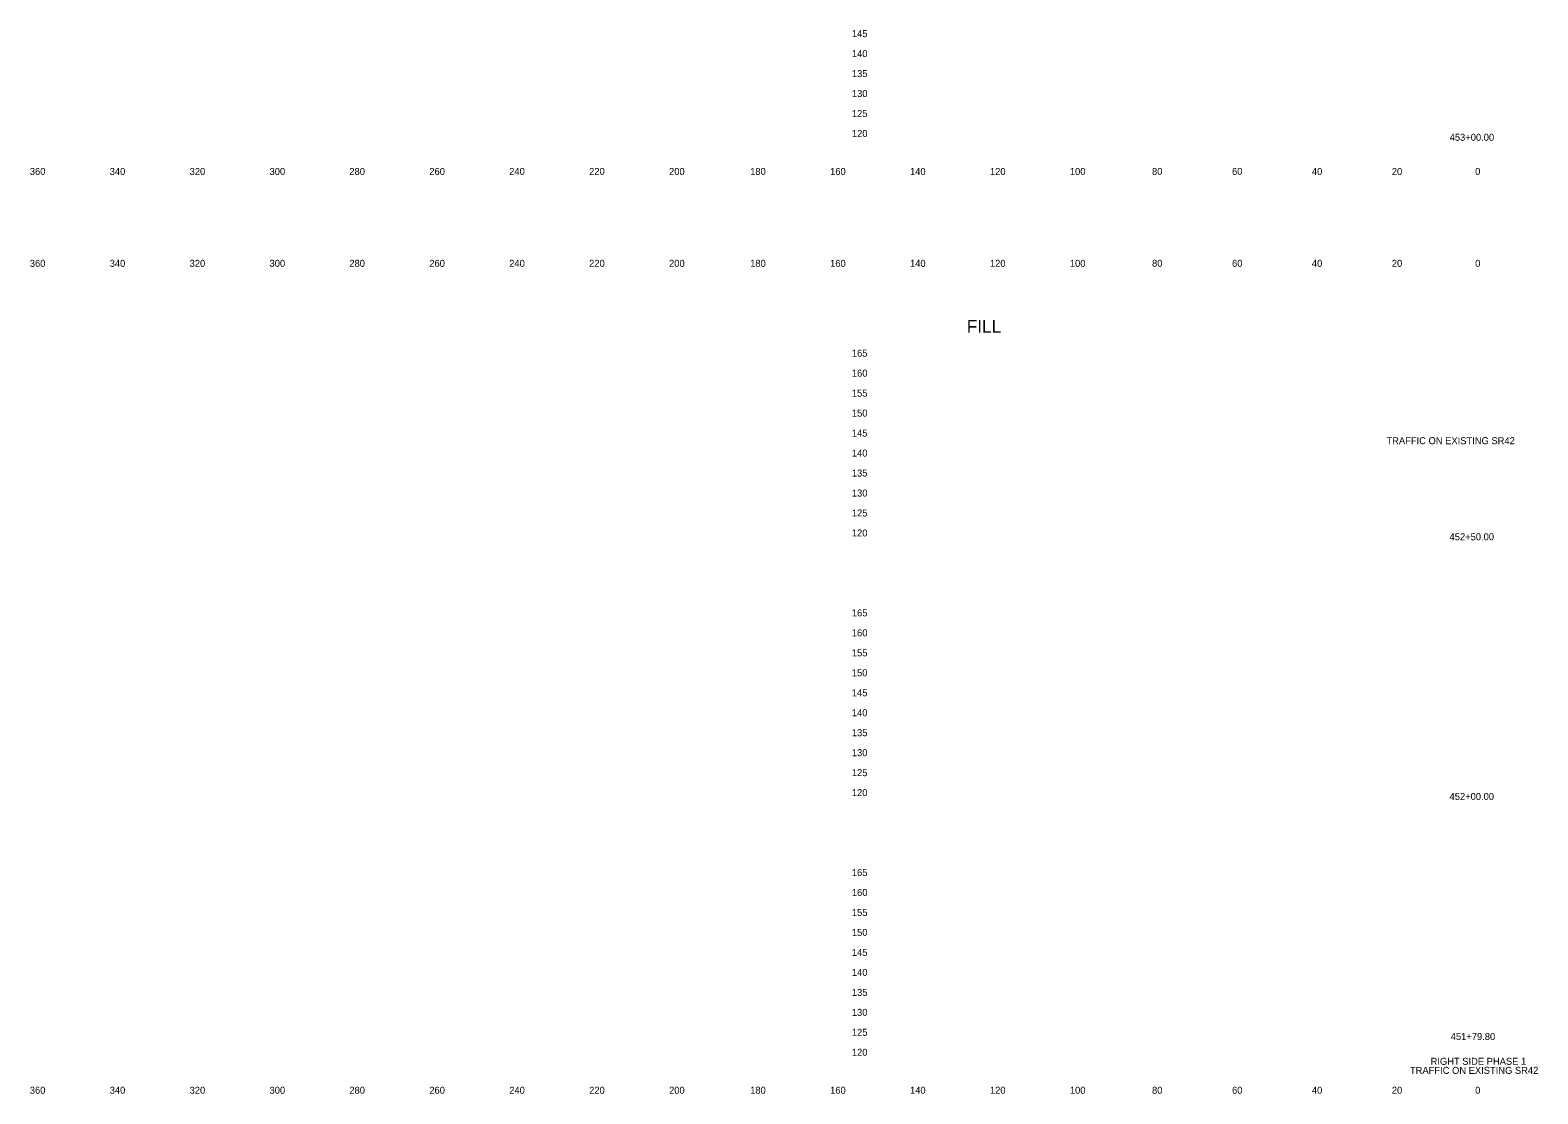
# Model space of a CAD drawing. Extents: x 21281 to 22024, y 6472 to 15198.
# Drawn here: x 21280.5 to 21657.8, y 6475.3 to 6741.6 of the extents above; entities that cross this region are included whole.
import ezdxf

# ---------------------------------------------------------------- set-up
doc = ezdxf.new("R2010")
doc.units = 0
for name, color, linetype in [('XS_SHEET_LABELS_ELEVATION', 7, 'Continuous'), ('XS_SHEET_LABELS_OFFSET', 7, 'Continuous'), ('XS_SHEET_LABELS_STATION', 7, 'Continuous')]:
    doc.layers.add(name, color=color, linetype=linetype)

msp = doc.modelspace()

# ---------------------------------------------------------------- texts
at = {"layer": 'XS_SHEET_LABELS_ELEVATION'}
for s, p in [('  145  ', (21484.84, 6739.84)), ('  140  ', (21484.84, 6734.84)), ('  135  ', (21484.84, 6729.84)), ('  130  ', (21484.84, 6724.84)), ('  125  ', (21484.84, 6719.84)), ('  120  ', (21484.84, 6714.84)), ('  165  ', (21484.84, 6659.84)), ('  160  ', (21484.84, 6654.84)), ('  155  ', (21484.84, 6649.84)), ('  150  ', (21484.84, 6644.84)), ('  145  ', (21484.84, 6639.84)), ('  140  ', (21484.84, 6634.84)), ('  135  ', (21484.84, 6629.84)), ('  130  ', (21484.84, 6624.84)), ('  125  ', (21484.84, 6619.84)), ('  120  ', (21484.84, 6614.84)), ('  165  ', (21484.84, 6594.84)), ('  160  ', (21484.84, 6589.84)), ('  155  ', (21484.84, 6584.84)), ('  150  ', (21484.84, 6579.84)), ('  145  ', (21484.84, 6574.84)), ('  140  ', (21484.84, 6569.84)), ('  135  ', (21484.84, 6564.84)), ('  130  ', (21484.84, 6559.84)), ('  125  ', (21484.84, 6554.84)), ('  120  ', (21484.84, 6549.84)), ('  165  ', (21484.84, 6529.84)), ('  160  ', (21484.84, 6524.84)), ('  155  ', (21484.84, 6519.84)), ('  150  ', (21484.84, 6514.84)), ('  145  ', (21484.84, 6509.84)), ('  140  ', (21484.84, 6504.84)), ('  135  ', (21484.84, 6499.84)), ('  130  ', (21484.84, 6494.84)), ('  125  ', (21484.84, 6489.84)), ('  120  ', (21484.84, 6484.84))]:
    msp.add_text(s, height=1.75, dxfattribs=at).set_placement(p)
at = {"layer": 'XS_SHEET_LABELS_OFFSET'}
for s, height, p in [('  360  ', 1.75, (21279.14, 6705.34)), ('  340  ', 1.75, (21299.13, 6705.34)), ('  320  ', 1.75, (21319.13, 6705.34)), ('  300  ', 1.75, (21339.13, 6705.34)), ('  280  ', 1.75, (21359.1, 6705.34)), ('  260  ', 1.75, (21379.11, 6705.34)), ('  240  ', 1.75, (21399.1, 6705.34)), ('  220  ', 1.75, (21419.1, 6705.34)), ('  200  ', 1.75, (21439.1, 6705.34)), ('  180  ', 1.75, (21459.39, 6705.34)), ('  160  ', 1.75, (21479.4, 6705.34)), ('  140  ', 1.75, (21499.39, 6705.34)), ('  120  ', 1.75, (21519.39, 6705.34)), ('  100  ', 1.75, (21539.39, 6705.34)), ('  80  ', 1.75, (21559.95, 6705.34)), ('  60  ', 1.75, (21579.97, 6705.34)), ('  40  ', 1.75, (21599.95, 6705.34)), ('  20  ', 1.75, (21619.95, 6705.34)), ('  0  ', 1.75, (21640.81, 6705.34)), ('  0  ', 1.75, (21640.81, 6705.34)), ('  360  ', 1.75, (21279.14, 6682.34)), ('  340  ', 1.75, (21299.13, 6682.34)), ('  320  ', 1.75, (21319.13, 6682.34)), ('  300  ', 1.75, (21339.13, 6682.34)), ('  280  ', 1.75, (21359.1, 6682.34)), ('  260  ', 1.75, (21379.11, 6682.34)), ('  240  ', 1.75, (21399.1, 6682.34)), ('  220  ', 1.75, (21419.1, 6682.34)), ('  200  ', 1.75, (21439.1, 6682.34)), ('  180  ', 1.75, (21459.39, 6682.34)), ('  160  ', 1.75, (21479.4, 6682.34)), ('  140  ', 1.75, (21499.39, 6682.34)), ('  120  ', 1.75, (21519.39, 6682.34)), ('  100  ', 1.75, (21539.39, 6682.34)), ('  80  ', 1.75, (21559.95, 6682.34)), ('  60  ', 1.75, (21579.97, 6682.34)), ('  40  ', 1.75, (21599.95, 6682.34)), ('  20  ', 1.75, (21619.95, 6682.34)), ('  0  ', 1.75, (21640.81, 6682.34)), ('  0  ', 1.75, (21640.81, 6682.34)), ('FILL', 3.222, (21514.89, 6665.82)), ('  360  ', 1.75, (21279.14, 6475.34)), ('  340  ', 1.75, (21299.13, 6475.34)), ('  320  ', 1.75, (21319.13, 6475.34)), ('  300  ', 1.75, (21339.13, 6475.34)), ('  280  ', 1.75, (21359.1, 6475.34)), ('  260  ', 1.75, (21379.11, 6475.34)), ('  240  ', 1.75, (21399.1, 6475.34)), ('  220  ', 1.75, (21419.1, 6475.34)), ('  200  ', 1.75, (21439.1, 6475.34)), ('  180  ', 1.75, (21459.39, 6475.34)), ('  160  ', 1.75, (21479.4, 6475.34)), ('  140  ', 1.75, (21499.39, 6475.34)), ('  120  ', 1.75, (21519.39, 6475.34)), ('  100  ', 1.75, (21539.39, 6475.34)), ('  80  ', 1.75, (21559.95, 6475.34)), ('  60  ', 1.75, (21579.97, 6475.34)), ('  40  ', 1.75, (21599.95, 6475.34)), ('  20  ', 1.75, (21619.95, 6475.34)), ('  0  ', 1.75, (21640.81, 6475.34)), ('  0  ', 1.75, (21640.81, 6475.34))]:
    msp.add_text(s, height=height, dxfattribs=at).set_placement(p)
at = {"layer": 'XS_SHEET_LABELS_STATION'}
for s, p in [('  453+00.00  ', (21634.43, 6713.89)), ('TRAFFIC ON EXISTING SR42', (21619.91, 6637.94)), ('  452+50.00  ', (21634.4, 6613.89)), ('  452+00.00  ', (21634.4, 6548.89)), ('  451+79.80  ', (21634.69, 6488.79)), ('TRAFFIC ON EXISTING SR42', (21625.79, 6480.32)), ('RIGHT SIDE PHASE 1', (21630.95, 6482.58))]:
    msp.add_text(s, height=1.75, dxfattribs=at).set_placement(p)

doc.saveas('drawing.dxf')
